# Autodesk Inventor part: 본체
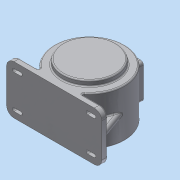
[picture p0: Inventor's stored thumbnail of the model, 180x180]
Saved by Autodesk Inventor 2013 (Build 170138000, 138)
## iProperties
Created: 2415-06
Part Number: 본체
Material: 알루미늄 6061
Document SubType Name: Modeling
Designer: Administrator
Density: 2.71 g/cm^3
Mass: 3262.64 g
Surface Area: 2294.84 cm^2
Volume: 1203.93 cm^3
Author: Administrator
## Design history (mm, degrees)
sketch "스케치1"
  geometry: C1 r 85 at (0, 0); 1 further point
  constraints: 1 centre point, 1 coincident
  dimensions: "d0" = 170 diameter of C1
extrude "돌출1" new body sketch "스케치1" stored distance "d3" = 118; taper "d4" = 0 deg
sketch "스케치2"
  geometry: C1 r 85 at (0, 0) reference; C2 r 65 at (0, 0)
  constraints: 1 centre point, 1 coincident
  dimensions: "d5" = 130 diameter of C2
extrude "돌출2" join sketch "스케치2" distance "d7" = 13; taper "d8" = 0 deg
sketch "스케치3"
  geometry: C1 r 85 at (0, 0) reference; C2 r 65 at (0, 0)
  constraints: 1 centre point, 1 coincident
  dimensions: "d9" = 130 diameter of C2
extrude "돌출3" join sketch "스케치3" distance "d11" = 3; taper "d12" = 0 deg
node "작업 평면1"
sketch "스케치4"
  geometry: L1 (-97, -59)-(97, -59); L2 (115, -41)-(115, 41); L3 (97, 59)-(-97, 59); L4 (-115, 41)-(-115, -41); L5 (-115, -59)-(115, 59); L6 (115, -59)-(-115, 59); A1 r 18 centre (-97, 41) between (-97, 59) and (-115, 41); A2 r 18 centre (-97, -41) between (-115, -41) and (-97, -59); A3 r 18 centre (97, -41) between (97, -59) and (115, -41); A4 r 18 centre (97, 41) between (115, 41) and (97, 59); 3 further points
  constraints: 12 end point, 8 point on circle, 8 point on line, 8 tangent, 4 centre point, 3 equal radius, 3 midpoint, 2 parallel, 1 coincident, 1 horizontal, 1 perpendicular
  dimensions: "d14" = 230 distance of L6.end L5.end; "d15" = 118 distance of L5.end L6.start; "d16" = 18 radius of A1
extrude "돌출4" join sketch "스케치4" distance "d17" = 14; taper "d18" = 0 deg
sketch "스케치5"
  geometry: L1 (0, 41)-(0, -41); L2 (97, 41)-(97, -41); L3 (-97, 41)-(-97, -41); L4 (-97, 50)-(-81, 50); L5 (-97, 32)-(-81, 32); L6 (-81, 45)-(-97, 45); L7 (-97, 37)-(-81, 37); A1 r 9 centre (-97, 41) between (-97, 50) and (-97, 32); A2 r 9 centre (-81, 41) between (-81, 32) and (-81, 50); A3 r 4 centre (-97, 41) between (-97, 45) and (-97, 37); A4 r 4 centre (-81, 41) between (-81, 37) and (-81, 45); 2 further points
  constraints: 14 end point, 8 point on circle, 4 centre point, 4 parallel, 2 coincident, 2 tangent, 1 midpoint, 1 perpendicular, 1 vertical, 3 other
  dimensions: "d19" = 82 distance of L1.start L1.end; "d20" = 97 distance between parallel lines of L3 L1; "d21" = 97 distance between parallel lines of L2 L1 (= d20); "d22" = 18 diameter of A1; "d23" = 16 distance of L4.start L4.end; "d24" = 16 distance of L5.start L5.end; "d25" = 97 distance of L1.start L3.start; "d26" = 81 distance of L1.start A2.centre; "d27" = 8 distance between parallel lines of L6 L7
extrude "돌출5" cut sketch "스케치5" stored distance "d28" = 14; taper "d29" = 0 deg
extrude "돌출6" join sketch "스케치5" distance "d30" = 3; taper "d31" = 0 deg
fillet "모깎기1" dims "d32" = 3
hole "구멍1" diameter "d35" = 95; stored, may be unused: countersink angle "d39" = 90 deg, drill point angle "d41" = 0 deg; dims "d33" = 10, "d34" = 10, "d36" = 6, "d37" = 95, "d38" = 11, "d40" = 11
hole "구멍2" diameter "d44" = 154; stored, may be unused: countersink angle "d48" = 90 deg, drill point angle "d50" = 0 deg; dims "d45" = 6, "d46" = 95, "d47" = 11, "d49" = 98.5, "d120" = 10, "d121" = 10
hole "구멍3" diameter "d53" = 30; stored, may be unused: countersink angle "d57" = 90 deg, drill point angle "d59" = 0 deg; dims "d51" = 10, "d52" = 10, "d54" = 6, "d55" = 47, "d56" = 14, "d58" = 17
node "작업 평면2"
sketch "스케치6"
  geometry: L1 (-35.5, -42.5)-(35.5, -42.5); L2 (42.5, -35.5)-(42.5, 35.5); L3 (35.5, 42.5)-(-35.5, 42.5); L4 (-42.5, 35.5)-(-42.5, -35.5); L5 (-42.5, -42.5)-(42.5, 42.5); L6 (42.5, -42.5)-(-42.5, 42.5); A1 r 7 centre (-35.5, 35.5) between (-35.5, 42.5) and (-42.5, 35.5); A2 r 7 centre (-35.5, -35.5) between (-42.5, -35.5) and (-35.5, -42.5); A3 r 7 centre (35.5, -35.5) between (35.5, -42.5) and (42.5, -35.5); A4 r 7 centre (35.5, 35.5) between (42.5, 35.5) and (35.5, 42.5); 1 further point
  constraints: 12 end point, 8 point on circle, 8 point on line, 8 tangent, 4 centre point, 3 equal radius, 2 midpoint, 2 parallel, 1 horizontal, 1 perpendicular
  dimensions: "d61" = 85 distance of L5.end L6.end; "d63" = 85 distance of L6.start L5.end; "d64" = 7 radius of A1
extrude "돌출7" join sketch "스케치6" stored distance "d65" = 3; taper "d66" = 0 deg
sketch "스케치7"
  geometry: C1 r 35 at (0, 0); 1 further point
  constraints: 1 centre point, 1 coincident
  dimensions: "d67" = 70 diameter of C1
extrude "돌출8" cut sketch "스케치7" stored distance "d69" = 3; taper "d70" = 0 deg
sketch "스케치8"
  geometry: A1 r 55 centre (0, 0) between (0, 55) and (-55, 0); 3 further points
  constraints: 4 point on circle, 2 horizontal alignment, 2 vertical alignment, 1 centre point
  dimensions: "d71" = 110 diameter of A1
hole "구멍4" sketch "스케치8" at (0, 55), (-55, 0), (0, -55), (55, 0) diameter "d73" = 3.242; stored, may be unused: countersink angle "d77" = 90 deg, drill point angle "d79" = 0 deg; dims "d74" = 6, "d75" = 19.05, "d76" = 4.775, "d78" = 17
hole "구멍5" diameter "d82" = 3.242; stored, may be unused: countersink angle "d86" = 90 deg, drill point angle "d88" = 118 deg; dims "d83" = 10, "d84" = 19.05, "d85" = 4.775, "d87" = 13, "d167" = 10, "d168" = 10
hole "구멍6" diameter "d91" = 3.242; stored, may be unused: countersink angle "d95" = 90 deg, drill point angle "d97" = 118 deg; dims "d92" = 10, "d93" = 19.05, "d94" = 4.775, "d96" = 13, "d169" = 10, "d170" = 10
hole "구멍7" diameter "d100" = 3.242; stored, may be unused: countersink angle "d104" = 90 deg, drill point angle "d106" = 118 deg; dims "d101" = 10, "d102" = 19.05, "d103" = 4.775, "d105" = 13, "d171" = 10, "d172" = 10
hole "구멍8" diameter "d109" = 3.242; stored, may be unused: countersink angle "d113" = 90 deg, drill point angle "d115" = 118 deg; dims "d110" = 10, "d111" = 19.05, "d112" = 4.775, "d114" = 13, "d173" = 10, "d174" = 10
fillet "모깎기2" dims "d116" = 0.3
fillet "모깎기4" dims "d118" = 3
fillet "모깎기5" dims "d119" = 3
sketch "스케치9"
  geometry: L1 (-77, 47.5)-(77, 47.5) reference; L2 (0, -67.8)-(0, 70.8) reference; L3 (77, 51)-(77, 47.5); L4 (77, 47.5)-(77, -48) reference; L5 (31, 47.5)-(31, 51); L6 (31, 51)-(29.368, 47.5); L7 (31, 51)-(77, 51); 1 further point
  constraints: 8 end point, 2 parallel, 2 point on line, 1 perpendicular
  dimensions: "d123" = 62 diameter of L5 L2; "d126" = 3.5 distance of L3.start L1.end; "d127" = 115 deg angle of L7 L6
revolve "회전1" sketch "스케치9" stored, may be unused: angle "d128" = 90 deg
sketch "스케치10"
  geometry: 1 further point
fillet "모깎기6" dims "d129" = 3
chamfer "모따기1" distance "d130" = 1; stored, may be unused: second distance "d131" = 2, angle "d132" = 45 deg
chamfer "모따기2" distance "d133" = 1; stored, may be unused: second distance "d134" = 2, angle "d135" = 45 deg
sketch "스케치11"
  geometry: L1 (-115, -85)-(-115, -71) reference; L2 (-97, -71)-(-115, -71) reference; L3 (-97, -71)-(-81, -71) reference; L4 (-115, -85)-(-97, -85) reference; L5 (-109, -71)-(-109, -85); L6 (-69, -71)-(-81, -71) reference; L7 (-46.733, -71)-(-97, -71) reference; L8 (-109, -71)-(-84.87, -4.703); A1 r 85 centre (0, 0) between (46.733, -71) and (-46.733, -71) reference; 1 further point
  constraints: 4 end point, 2 point on line, 1 perpendicular, 1 point on circle
  dimensions: "d141" = 6 distance between parallel lines of L5 L1; "d142" = 110 deg angle of L8 L2
extrude "돌출10" join sketch "스케치11" stored distance "d143" = 15; taper "d144" = 0 deg
fillet "모깎기7" dims "d145" = 3
fillet "모깎기8"
fillet "모깎기9"
fillet "모깎기10" dims "d146" = 3
fillet "모깎기11" dims "d147" = 3
sketch "스케치12"
  geometry: L1 (-161, 0)-(161, 0) reference; L2 (0, 0)-(182.329, 85.021); L3 (56.726, 79.477)-(94.457, -1.436); A1 r 85 centre (0, 0) between (53.953, -65.682) and (-53.953, -65.682) reference
  constraints: 4 end point, 1 perpendicular, 1 tangent
  dimensions: "d148" = 25 deg angle of L2 L1; "d149" = 201.17745 distance of L2.start L2.end; "d150" = 89.27744 distance of L3.start L3.end
node "작업 평면3"
fillet "모깎기12" dims "d154" = 3
sketch "스케치14"
  geometry: L1 (0, 0)-(-115.997, 54.09); L2 (-176.87, 0)-(242.195, 0) reference; L3 (-65.415, 60.843)-(-88.657, 11.002); A1 r 85 centre (0, 0) between (53.953, -65.682) and (-53.953, -65.682) reference; 1 further point
  constraints: 4 end point, 1 midpoint, 1 perpendicular, 1 point on line, 1 tangent
  dimensions: "d155" = 25 deg angle of L1 L2; "d158" = 115.9966 horizontal distance of L1.start L1.end; "d159" = 54.99423 distance of L3.start L3.end
node "작업 평면4"
sketch "스케치15"
  geometry: 2 further points
  constraints: 1 coincident, 1 other
feature "엠보싱2" sketch "스케치15" dims "d160" = 0.5, "d161" = 0
chamfer "모따기3" distance "d162" = 1; stored, may be unused: second distance "d163" = 2, angle "d164" = 45 deg
fillet "모깎기13" dims "d165" = 3
fillet "모깎기14" dims "d166" = 0.3
node "솔리드1"
mirror "대칭1"
mirror "대칭2"
mirror "대칭3"
other parameters: "d13" = -85, "d60" = 88, "d122" = 3.5, "d125" = 115 deg, "d151" = 90 deg
